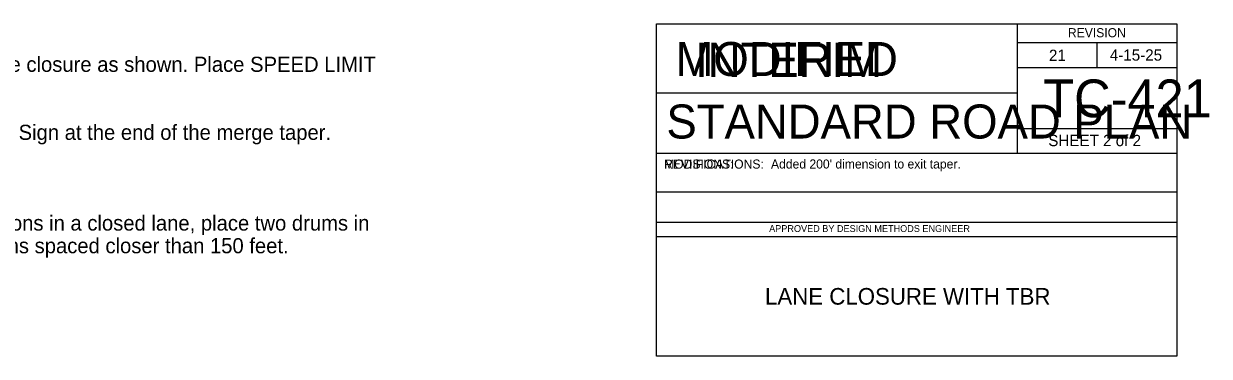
# Model space of a CAD drawing. Extents: x 10133 to 2270741, y 5363 to 1733450.
# Drawn here: x 29731 to 31300, y 5363 to 5803 of the extents above; entities that cross this region are included whole.
import ezdxf

# ---------------------------------------------------------------- set-up
doc = ezdxf.new("R2010")
doc.units = 0
for name, color, linetype in [('dsnStdDimension', 7, 'Continuous'), ('dsnStdLineWork', 7, 'Continuous'), ('dsnStdShading', 7, 'Continuous'), ('dsnStdTable', 7, 'Continuous'), ('StdNote', 7, 'Continuous'), ('StdNoteLinks', 7, 'Continuous')]:
    doc.layers.add(name, color=color, linetype=linetype)

msp = doc.modelspace()

# ---------------------------------------------------------------- linework, layer by layer
at = {"layer": 'dsnStdDimension'}
for p, q in [((31045.6, 5802.8), (31045.6, 5711.5)), ((31045.6, 5777.9), (31256.6, 5777.9)), ((31151.1, 5777.9), (31151.1, 5744.7)), ((31045.6, 5744.7), (31256.6, 5744.7)), ((30568.5, 5711.5), (31045.6, 5711.5)), ((31045.6, 5711.5), (31045.6, 5631.4)), ((31256.6, 5663.6), (31045.6, 5663.6)), ((30568.5, 5631.4), (31256.6, 5631.4)), ((30568.5, 5580.4), (31256.6, 5580.4)), ((30568.5, 5540.4), (31256.6, 5540.4)), ((30568.5, 5521.4), (31256.6, 5521.4))]:
    msp.add_line(p, q, dxfattribs=at)
msp.add_lwpolyline([(30568.5, 5802.8), (31256.6, 5802.8), (31256.6, 5362.8), (30568.5, 5362.8)], close=True, dxfattribs=at)
at = {"layer": 'dsnStdLineWork'}
msp.add_lwpolyline([(30568.5, 5802.8), (31256.6, 5802.8), (31256.6, 5362.8), (30568.5, 5362.8)], close=True, dxfattribs=at)

# ---------------------------------------------------------------- texts
at = {"layer": 'dsnStdDimension'}
for s, height, p in [('REVISION', 12, (31112.6, 5784.9)), ('21', 15, (31087.6, 5753.4)), ('4-15-25', 15, (31168.1, 5753.9)), ('TC-421', 50, (31080, 5679)), ('STANDARD ROAD PLAN', 45.001, (30581.6, 5650.9)), ('SHEET 2 of 2', 15, (31086.7, 5640.8)), ("Added 200' dimension to exit taper.", 12, (30719.9, 5611.2)), ('APPROVED BY DESIGN METHODS ENGINEER', 9.003, (30717.5, 5527.3)), ('LANE CLOSURE WITH TBR', 22, (30712, 5431.1))]:
    msp.add_text(s, height=height, dxfattribs=at).set_placement(p)
at = {"layer": 'dsnStdShading'}
msp.add_text('REVISIONS:', height=12, dxfattribs=at).set_placement((30578.5, 5611.1))
at = {"layer": 'dsnStdTable'}
for s, p in [('Place SPEED LIMIT AHEAD sign and SPEED LIMIT 55 sign prior to the lane closure as shown. Place SPEED LIMIT', (28817.9, 5739.1)), ('For traffic control zones lasting more than 4 hours, place a Speed Feedback Sign at the end of the merge taper.', (28817.9, 5649.1)), ('For lanes closed to traffic, place two drums every 1000 feet. For full depth excavations in a closed lane, place two drums in ', (28737.9, 5529.1)), ('front of each location. Additional drums need not be placed for full depth excavations spaced closer than 150 feet.', (28737.9, 5499.1))]:
    msp.add_text(s, height=20, dxfattribs=at).set_placement(p)
at = {"layer": 'StdNote'}
msp.add_text('INTERIM', height=45, dxfattribs=at).set_placement((30619.5, 5732.5))
at = {"layer": 'StdNoteLinks'}
for s, height, p in [('MODIFIED', 45, (30593.6, 5733.6)), ('MODIFICATIONS:', 12, (30578.5, 5611.1))]:
    msp.add_text(s, height=height, dxfattribs=at).set_placement(p)

doc.saveas('drawing.dxf')
